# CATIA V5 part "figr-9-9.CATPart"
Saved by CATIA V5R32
Part number: Part1
Bounding box of the stored display mesh (mm): x -15.705 to 88.369, y 0 to 286.83, z -20.723 to 20.723
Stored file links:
  D:\PROJECTS\Project 2022\CATIA V5 6R 2022\Resources\Part Files\c09_catia_v5_6r2022_prt\c09_catia_v5_6r2022_prt\figr-9-9.CATPart
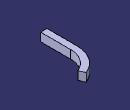
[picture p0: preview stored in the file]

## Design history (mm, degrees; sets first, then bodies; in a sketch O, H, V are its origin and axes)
Body1 (main body)
  Sketch1 on xy-plane, origin (0, 0, 0), H (1, 0, 0), V (0, 1, 0)
    line L1 (0, 0) -> (0, 150)
    arc A1 centre (131.8599, 150) radius 131.8599 from (0, 150) to (82.4884, 272.2681) cw
    length L1 = 150
    tangency: A1 L1
  Sketch2 on zx-plane, origin (0, 0, 0), H (-1, 0, 0), V (0, 0, 1)
    line L1 (15.7048, 20.7231) -> (15.7048, -20.7231)
    line L2 (15.7048, -20.7231) -> (-15.7048, -20.7231)
    line L3 (-15.7048, -20.7231) -> (-15.7048, 20.7231)
    line L4 (-15.7048, 20.7231) -> (15.7048, 20.7231)
    vertical: L1 V, L3 V
    horizontal: L2 H, L4 H
    equidistance: L1 L3 O, L2 L4 O
  Rib1: profile Sketch2, centre curve Sketch1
